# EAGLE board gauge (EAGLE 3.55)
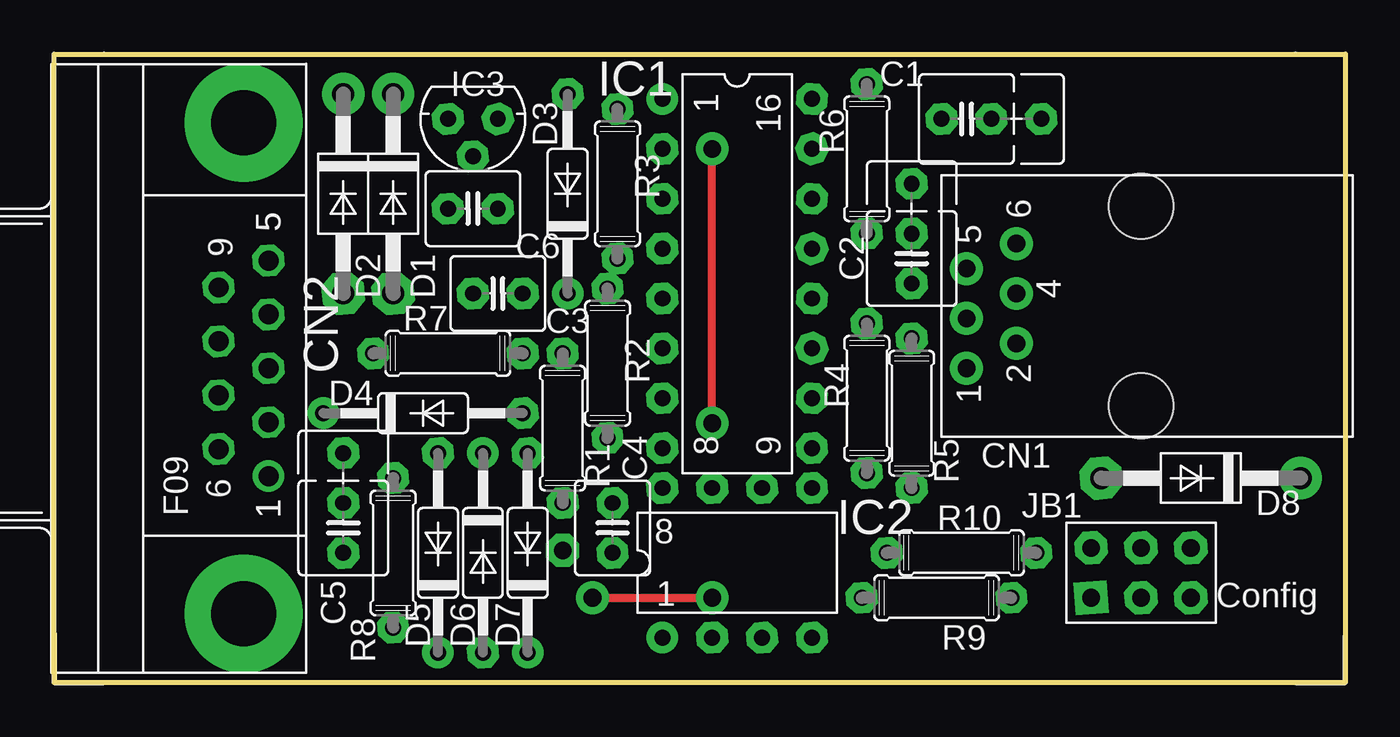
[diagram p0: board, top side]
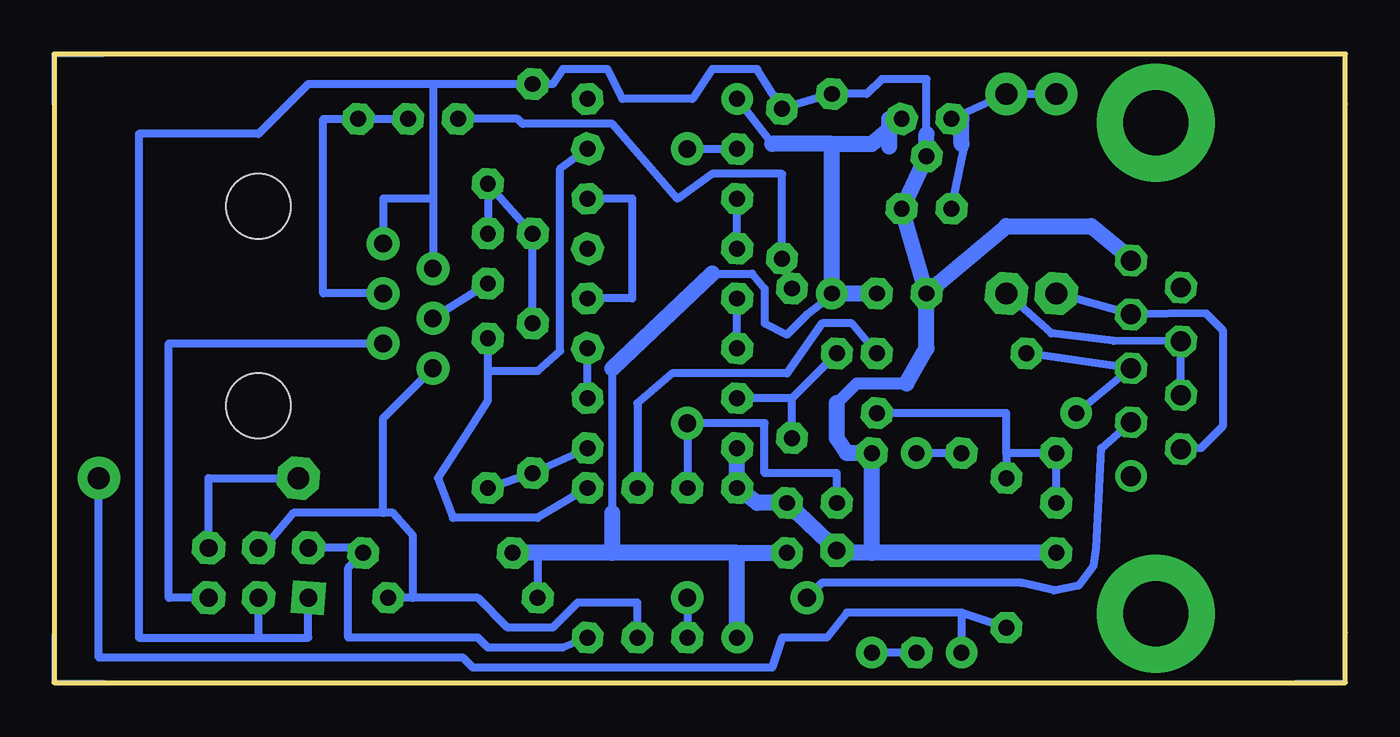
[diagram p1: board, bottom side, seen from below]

Size 65.79 x 32 mm. Coordinates in mm from the lower left corner, seen from the top.
Outline: 0,0 0,32 65.79,32 65.79,0 0,0
Copper layers used: Top, Bottom

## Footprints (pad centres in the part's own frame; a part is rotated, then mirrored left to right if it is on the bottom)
,5/5-5 = drill 0.813 pad 1.6 octagon:  -2.54,0;  2.54,0;  0,0
,5-4 = drill 0.813 pad 1.6 octagon:  -1.27,0;  1.27,0
D66 = drill 0.9 pad 1.676 round:  1.27,-2.54;  0,0;  3.81,-2.54;  6.35,-2.54;  2.54,0;  5.08,0 | hole 3.3: -1.905,-8.89; 8.255,-8.89
9H = drill 1.016 pad 1.6 round:  -5.486,-1.27 | drill 1.016 pad 1.6 octagon:  -2.743,-1.27;  0,-1.27;  2.743,-1.27;  5.486,-1.27;  -4.115,1.27;  -1.372,1.27;  1.372,1.27;  4.115,1.27 | drill 3.3 pad 6 round:  12.5,0;  -12.5,0
41-10 = drill 1.118 pad 2.159 octagon:  5.08,0 | drill 1.118 pad 2.159 round:  -5.08,0
35-10 = drill 0.813 pad 1.6 round:  -5.08,0 | drill 0.813 pad 1.6 octagon:  5.08,0
L16 = drill 0.813 pad 1.6 round:  -8.89,-3.81 | drill 0.813 pad 1.6 octagon:  -6.35,-3.81;  -3.81,-3.81;  -1.27,-3.81;  1.27,-3.81;  3.81,-3.81;  6.35,-3.81;  8.89,-3.81;  8.89,3.81;  6.35,3.81;  3.81,3.81;  1.27,3.81;  -1.27,3.81;  -3.81,3.81;  -6.35,3.81;  -8.89,3.81
L8 = drill 0.813 pad 1.6 round:  -3.81,-3.81 | drill 0.813 pad 1.6 octagon:  -1.27,-3.81;  1.27,-3.81;  3.81,-3.81;  3.81,3.81;  1.27,3.81;  -1.27,3.81;  -3.81,3.81
LXX = drill 0.813 pad 1.6 octagon:  -1.27,0;  0,1.905;  1.27,0
6 = drill 0.9 pad 1.676 square:  0,0 | drill 0.9 pad 1.676 octagon:  0,2.54;  2.54,0;  2.54,2.54;  5.08,0;  5.08,2.54
07/7 = drill 0.813 pad 1.6 octagon:  -3.81,0;  3.81,0

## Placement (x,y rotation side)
C1  10n  [,5/5-5]  47.75,28.7 0 top
C2  10n  [,5/5-5]  43.69,22.86 90 top
C3  100n  [,5-4]  22.61,19.81 0 top
C4  100n  [,5-4]  28.45,7.87 270 top
C5  47u  [,5/5-5]  14.73,9.14 90 top
C6  100n  [,5-4]  21.34,24.13 180 top
CN1  Gauge  [D66]  46.48,16 90 top
CN2  F09HG  [9H]  9.65,16 90 top
D1  1N4001  [41-10]  17.27,24.89 270 top
D2  1N4001  [41-10]  14.73,24.89 270 top
D3  5.1V  [35-10]  26.16,24.89 90 top
D4  1N4148  [35-10]  18.8,13.72 0 top
D5  1N4148  [35-10]  19.56,6.6 90 top
D6  1N4148  [35-10]  21.84,6.6 270 top
D7  1N4148  [35-10]  24.13,6.6 90 top
D8  1N4001  [41-10]  58.42,10.41 180 top
IC1  4049  [L16]  34.8,20.83 270 top
IC2  12C509P  [L8]  34.8,6.1 0 top
IC3  78L05  [LXX]  21.34,28.7 180 top
JB1  Config  [6]  52.83,4.32 0 top
R1  1M  [07/7]  25.91,12.95 270 top
R2  100k  [07/7]  28.19,16.26 270 top
R3  330k  [07/7]  28.7,25.4 90 top
R4  1M  [07/7]  43.69,13.72 90 top
R5  100k  [07/7]  41.4,14.48 270 top
R6  330k  [07/7]  41.4,26.67 90 top
R7  10k  [07/7]  20.07,16.76 180 top
R8  2k2  [07/7]  17.27,6.6 90 top
R9  100k  [07/7]  44.96,4.32 180 top
R10  100k  [07/7]  46.23,6.6 180 top

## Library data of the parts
C1-C6 = CAP
CN1 CN2 JB1 = my_conn
D1-D8 = DIODE
IC1 = 40XX
IC2 = PIC
IC3 = V-REG
R1-R10 = R

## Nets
GND: C3. C4. C5. C6. CN1. CN2. D3. D7. IC1. IC2. IC3. JB1. R3. R6.
N$1: IC1.
N$2: IC1.
N$3: IC1.
N$4: IC1.
N$5: CN2. IC2.
N$6: IC1. R1. R2.
N$7: IC1. R4. R5.
N$8: C2. CN1.
N$9: C1. CN1.
N$10: IC1. IC2. R1.
N$11: CN2. D4. R7.
N$12: C1. R2. R3.
N$13: C2. R5. R6.
N$14: CN2. D2.
N$15: CN1. IC2. JB1. R9.
N$16: CN2. D1.
N$18: C6. D1. D2. IC3.
N$19: IC2. R7.
N$21: D6. D7.
N$22: IC1. IC2. R4.
N$23: D5. D6.
N$24: D5. D8. R8.
N$25: D8. JB1.
N$26: C5. D4. R8.
N$27: CN1. JB1.
N$29: IC2. JB1. R10.
VDD: C3. C4. D3. IC1. IC2. IC3. R9. R10.

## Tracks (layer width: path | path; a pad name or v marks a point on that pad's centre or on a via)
GND
  Bottom 0.406: R6. 40.89,30.48 | 55.37,2.29 55.37,4.32 | 55.37,2.29 61.47,2.29 61.47,27.94 55.37,27.94 52.83,30.48 46.48,30.48 | R6. 46.48,30.48 | 52.83,4.32 52.83,2.29 55.37,2.29 | R6. 40.39,30.48 39.88,31.24 37.59,31.24 36.83,29.72 33.27,29.72 32.26,31.24 29.97,31.24 R3. D3. 24.38,29.97 23.62,30.73 21.34,30.73 21.34,27.94 | 46.48,30.48 46.48,24.64 | 46.48,24.64 CN1. | 21.34,26.8 21.34,27.18 | 49.02,22.35 49.02,24.64 46.48,24.64
  Bottom 0.61: 25.91,14.22 24.89,15.24 22.35,15.24
  Bottom 0.813: 30.99,11.94 IC2. 29.97,9.14 28.45,9.14 25.78,6.6 24.13,6.6 | 22.35,15.24 21.34,17.02 21.34,19.81 | 21.34,27.94 21.34,26.8 22.61,24.13 21.34,19.81 | 14.73,6.6 24.13,6.6 | 24.13,6.6 D7. 25.4,11.68 25.91,12.45 25.91,14.22 | 21.34,19.81 17.27,23.24 12.95,23.24 10.92,21.59 10.92,21.49
N$1
  Bottom 0.406: 30.99,22.1 30.99,24.64
N$2
  Bottom 0.406: 30.99,17.02 30.99,19.56
N$3
  Bottom 0.406: 38.61,14.48 38.61,17.02
N$4
  Bottom 0.406: 38.61,19.56 36.32,19.56 36.32,24.64 38.61,24.64
N$5  (via drill 0.9 pad 1.68)
  Top 0.406: v27.43,4.32 v33.53,4.32
  Bottom 0.406: v27.43,4.32 26.67,5.08 16.51,5.08 14.86,4.7 13.59,4.95 12.83,5.97 12.7,6.86 12.45,11.94 10.92,13.26 | v33.53,4.32 33.53,2.29
N$6
  Bottom 0.406: 28.19,14.48 30.99,14.48 | R2. 28.19,14.48 | 28.19,14.48 25.91,16.76
N$7
  Bottom 0.406: 38.61,11.94 39.12,11.68 R5. 43.69,9.91
N$8
  Bottom 0.406: 43.69,20.32 46.48,18.54
N$9
  Bottom 0.406: 49.02,19.81 52.07,19.81 52.07,28.7 50.29,28.7 C1.
N$10  (via drill 0.9 pad 1.68)
  Top 0.406: v33.53,13.21 v33.53,27.18
  Bottom 0.406: R1. 25.91,10.67 29.59,10.67 29.59,13.21 v33.53,13.21 33.53,9.91 | v33.53,27.18 30.99,27.18
N$11
  Bottom 0.406: 13.72,13.72 10.92,16 R7.
N$12
  Bottom 0.406: 28.19,20.07 28.7,21.59 28.7,25.91 32.26,25.91 34.04,24.64 37.34,28.45 41.91,28.45 42.16,28.7 45.21,28.7
N$13
  Bottom 0.406: 41.4,18.29 41.4,22.86 43.69,25.4 C2.
N$14
  Bottom 0.406: 14.73,19.81 10.92,18.75 7.11,18.8 6.22,17.91 6.22,13.08 7.37,11.94 8.38,11.89
N$15
  Bottom 0.406: 55.37,6.86 55.12,6.86 53.59,8.64 49.02,8.64 | 47.5,4.32 47.5,7.49 48.51,8.64 49.02,8.64 | 47.5,4.32 48.77,4.32 | 36.07,2.29 36.07,4.06 39.12,4.06 40.39,2.79 42.67,2.79 44.2,4.32 47.5,4.32 | 46.48,16 49.02,13.46 49.02,8.64
N$16
  Bottom 0.406: 8.38,14.63 8.38,17.37 11.81,17.4 14.99,17.78 17.27,19.81
N$17
  Bottom 0.254: 0,2.54 0,0 2.54,0
N$18
  Bottom 0.406: D2. D1. IC3. 19.43,27.18 C6.
N$19
  Bottom 0.406: 36.07,9.91 36.07,14.22 34.29,15.75 28.45,15.75 26.67,18.29 25.15,18.29 23.88,16.76
N$20
  Bottom 0.254: 0,29.46 0,32 2.54,32
N$21
  Bottom 0.406: D6. 24.13,1.52
N$22
  Bottom 0.406: 38.61,9.91 41.15,8.38 45.47,8.38 46.23,10.41 44.58,12.95 43.69,14.35 43.69,15.87 | 43.69,15.87 R4. | 43.69,15.87 41.15,15.87 40,16.89 40,26.16 38.61,27.18
N$23
  Bottom 0.406: D5. 21.84,11.68
N$24
  Bottom 0.406: 19.56,3.56 19.56,1.52 | 19.56,3.56 25.4,3.56 26.42,2.29 28.7,2.29 29.21,0.76 44.45,0.76 44.96,1.27 63.5,1.27 D8. | 17.27,2.79 19.56,3.56
N$25
  Bottom 0.406: 53.34,10.41 57.91,10.41 JB1.
N$26
  Bottom 0.406: C5. 14.73,11.68 17.27,11.68 | 17.27,11.68 R8. | D4. 17.27,13.72 17.27,11.68
N$27
  Bottom 0.406: 57.91,4.32 59.94,4.32 59.94,17.27 49.02,17.27
N$28
  Bottom 0.254: 63.25,0 65.79,0 65.79,2.41
N$29
  Bottom 0.406: 38.61,2.29 39.88,1.78 43.69,1.78 44.2,2.29 50.8,2.29 50.8,5.84 50.04,6.6 50.29,6.86 52.83,6.86
N$31
  Bottom 0.813: 19.56,27.43 19.56,28.7
N$32
  Bottom 0.813: 23.24,27.3 23.24,28.7
N$33
  Bottom 0.254: 63.25,32 65.79,32 65.79,29.46
N$34  (via drill 0.9 pad 1.68)
  other vias: 25.91,6.73
VDD
  Bottom 0.406: 26.16,19.81 26.67,19.3 27.43,18.73 28.45,17.72 29.59,18.29 29.59,20.07 30.23,20.83 32.26,20.83 | 29.21,27.43 30.99,29.72 | 37.34,8.64 37.34,16 | 41.15,6.6 R9.
  Bottom 0.813: 30.99,2.29 30.99,6.6 | 30.99,6.6 C4. | 37.34,16 32.26,20.83 | 26.16,27.43 24.13,27.43 22.61,28.7 | 26.16,27.43 29.21,27.43 | 26.16,27.43 26.16,19.81 C3. | 30.99,6.6 37.34,6.6 | 37.34,6.6 41.15,6.6 R10. | 37.34,6.6 37.34,8.64

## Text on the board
_layer121: 1 | 16 | 6 | 5 | 5 | 9 | 5 | 4 | 2 | 1 | 8 | 9 | 6 | F09 | 1 | 1 | JB1 | 8 | 1 | Config
_layer125: IC3 | IC1 | C1 | D3 | R6 | R3 | C6 | D2 | D1 | C2 | R7 | C3 | R2 | CN2 | D4 | R4 | C4 | R5 | R1 | CN1 | D8 | R10 | IC2 | D6 | C5 | R9 | D5 | D7 | R8
_layer127: 1N4001 | 1N4001 | Gauge | 10n | 78L05 | 4049 | 330k | 100n | 5.1V | 330k | 10n | 100k | 100n | 10k | 100k | 1N4148 | 1M | 1N4148 | 1M | 1N4001 | F09HG | 100n | 100k | 47u | 1N4148 | 1N4148 | 100k | 2k2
